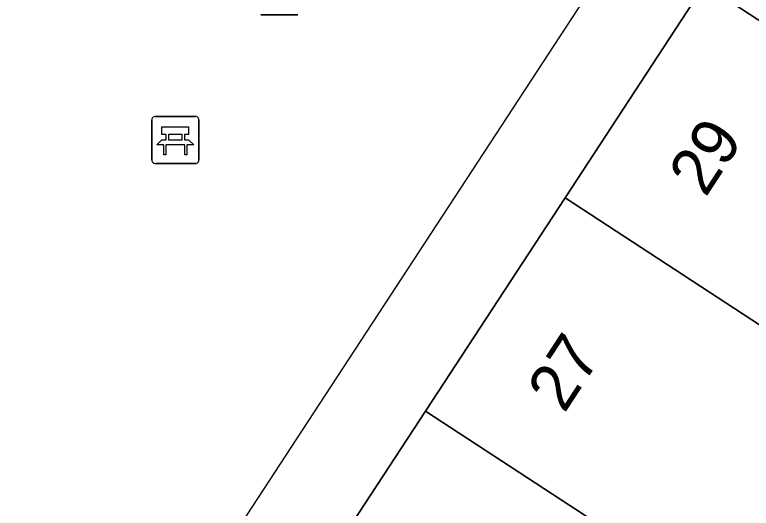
# Model space of a CAD drawing. Extents: x 155640 to 156811, y 382821 to 384049.
# Drawn here: x 156442.83 to 156458.45, y 383720.18 to 383730.65 of the extents above; entities that cross this region are included whole.
import ezdxf

# ---------------------------------------------------------------- set-up
doc = ezdxf.new("R2010")
doc.units = 0
for name, color, linetype in [('IMGEO_Bank', 7, 'Continuous'), ('IMGEO_Lichtmast', 7, 'Continuous'), ('IMGEO_Lijnafwatering', 7, 'Continuous'), ('IMGEO_Pand', 7, 'Continuous'), ('IMGEO_Pand_nummerreeks', 7, 'Continuous'), ('IMGEO_Voetgangersgebied_open', 7, 'Continuous')]:
    doc.layers.add(name, color=color, linetype=linetype)

msp = doc.modelspace()

# ---------------------------------------------------------------- linework, layer by layer
at = {"layer": 'IMGEO_Bank'}
for p, q in [((156445.736, 383727.566), (156445.736, 383728.407)), ((156445.736, 383728.407), (156445.736, 383727.566)), ((156445.811, 383728.491), (156446.652, 383728.491)), ((156446.652, 383728.491), (156445.811, 383728.491)), ((156446.736, 383728.416), (156446.736, 383727.575)), ((156446.736, 383727.575), (156446.736, 383728.416)), ((156446.045, 383727.997), (156446.045, 383728.103)), ((156446.089, 383728.103), (156446.089, 383727.997)), ((156446.377, 383728.109), (156446.095, 383728.109)), ((156446.383, 383727.997), (156446.383, 383728.103)), ((156446.427, 383728.103), (156446.427, 383727.997)), ((156446.095, 383727.991), (156446.377, 383727.991)), ((156446.433, 383727.889), (156446.04, 383727.889)), ((156446.661, 383727.491), (156445.82, 383727.491)), ((156445.82, 383727.491), (156446.661, 383727.491))]:
    msp.add_line(p, q, dxfattribs=at)
for points in [[(156446.039, 383728.109), (156445.953, 383728.109), (156445.953, 383728.27), (156446.516, 383728.27), (156446.516, 383728.109), (156446.433, 383728.109)], [(156445.983, 383727.889), (156445.841, 383727.889), (156445.953, 383727.991), (156446.039, 383727.991)], [(156446.433, 383727.991), (156446.516, 383727.991), (156446.628, 383727.889), (156446.489, 383727.889)], [(156446.033, 383727.882), (156446.033, 383727.675), (156445.99, 383727.675), (156445.99, 383727.882)], [(156446.483, 383727.882), (156446.483, 383727.675), (156446.439, 383727.675), (156446.439, 383727.882)]]:
    msp.add_lwpolyline(points, dxfattribs=at)
for centre, radius, start, end in [((156445.814, 383728.413), 0.0779, 92.4484, 184.2845), ((156445.814, 383728.413), 0.0779, 92.4484, 184.2845), ((156446.658, 383728.413), 0.0779, 2.4484, 94.2845), ((156446.658, 383728.413), 0.0779, 2.4484, 94.2845), ((156446.038, 383728.102), 0.00671, 2.8957, 87.1043), ((156446.095, 383728.102), 0.00671, 92.8957, 177.1043), ((156446.377, 383728.102), 0.00671, 2.8957, 87.1043), ((156446.434, 383728.102), 0.00671, 92.8957, 177.1043), ((156446.038, 383727.998), 0.00671, 272.8957, 357.1043), ((156446.095, 383727.998), 0.00671, 182.8957, 267.1043), ((156446.377, 383727.998), 0.00671, 272.8957, 357.1043), ((156446.434, 383727.998), 0.00671, 182.8957, 267.1043), ((156445.983, 383727.882), 0.00671, 2.8957, 87.1043), ((156446.04, 383727.882), 0.00671, 92.8957, 177.1043), ((156446.432, 383727.882), 0.00671, 2.8957, 87.1043), ((156446.489, 383727.882), 0.00671, 92.8957, 177.1043), ((156445.814, 383727.569), 0.0779, 182.4484, 274.2845), ((156445.814, 383727.569), 0.0779, 182.4484, 274.2845), ((156446.658, 383727.569), 0.0779, 272.4484, 4.2845), ((156446.658, 383727.569), 0.0779, 272.4484, 4.2845)]:
    msp.add_arc(centre, radius, start, end, dxfattribs=at)
at = {"layer": 'IMGEO_Lichtmast'}
for p, q in [((156448.837, 383730.645), (156448.047, 383730.645)), ((156448.047, 383730.645), (156448.837, 383730.645))]:
    msp.add_line(p, q, dxfattribs=at)
at = {"layer": 'IMGEO_Lijnafwatering'}
for points in [[(156459.635, 383738.197), (156449.169, 383722.207)], [(156449.169, 383722.207), (156437.575, 383704.494)]]:
    msp.add_lwpolyline(points, dxfattribs=at)
at = {"layer": 'IMGEO_Pand'}
for points in [[(156460.417, 383735.804), (156457.463, 383731.289), (156464.65, 383726.595), (156467.606, 383731.11)], [(156457.463, 383731.289), (156454.503, 383726.765), (156461.689, 383722.072), (156464.65, 383726.595)], [(156454.503, 383726.765), (156451.542, 383722.239), (156458.727, 383717.547), (156461.689, 383722.072)], [(156451.542, 383722.239), (156448.583, 383717.716), (156455.766, 383713.025), (156458.727, 383717.547)]]:
    msp.add_lwpolyline(points, close=True, dxfattribs=at)
at = {"layer": 'IMGEO_Voetgangersgebied_open'}
msp.add_lwpolyline([(156430.466, 383687.075), (156432.591, 383702.361), (156438.64, 383701.529), (156438.461, 383700.239), (156442.019, 383705.761), (156443.341, 383707.811), (156442.937, 383708.11), (156445.881, 383712.618), (156445.437, 383712.908), (156448.583, 383717.716), (156451.542, 383722.239), (156454.503, 383726.765), (156457.463, 383731.289), (156460.417, 383735.804), (156463.375, 383740.324), (156466.337, 383744.851), (156469.274, 383749.341)], dxfattribs=at)

# ---------------------------------------------------------------- texts
at = {"layer": 'IMGEO_Pand_nummerreeks'}
for s, rotation, p in [('29', 56.803, (156457.484, 383726.755)), ('27', 56.8088, (156454.487, 383722.175))]:
    msp.add_text(s, height=1, rotation=rotation, dxfattribs=at).set_placement(p)

doc.saveas('drawing.dxf')
